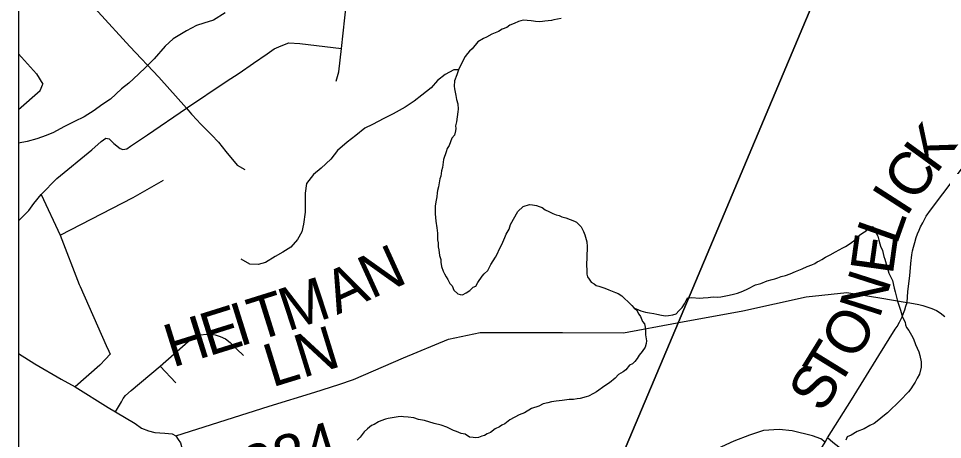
# Model space of a CAD drawing. Extents: x 0 to 34, y 0 to 22.
# Drawn here: x 2.1 to 3.321, y 17.998 to 18.554 of the extents above; entities that cross this region are included whole.
import ezdxf

# ---------------------------------------------------------------- set-up
doc = ezdxf.new("R2010")
doc.units = 0
for name, color, linetype in [('GM_X_Corporation', 7, 'Continuous'), ('GM_X_County_Road', 7, 'Continuous'), ('GM_X_County_Road_Text', 7, 'Continuous'), ('GM_X_Interchange_Ramps', 7, 'Continuous'), ('GM_X_Minor_River', 7, 'Continuous'), ('GM_X_Township_Road', 7, 'Continuous'), ('GM_X_Township_Road_Text', 7, 'Continuous'), ('SH_Data', 7, 'Continuous')]:
    doc.layers.add(name, color=color, linetype=linetype)

msp = doc.modelspace()

# ---------------------------------------------------------------- linework, layer by layer
at = {"layer": 'GM_X_Corporation'}
for points in [[(2.1, 20.9), (2.1, 16.0934), (2.225, 16.3897), (2.7544, 17.639), (2.811, 17.7726), (2.8255, 17.8068), (2.8709, 17.914), (2.886, 17.9497), (2.8909, 17.9612), (2.9719, 18.1533), (3.7872, 20.088)], [(3.7872, 20.088), (2.9719, 18.1533), (2.8909, 17.9612), (2.886, 17.9497), (2.8709, 17.914), (2.8255, 17.8068), (2.811, 17.7726), (2.7544, 17.639), (2.225, 16.3897), (2.1, 16.0934), (2.1, 14.8365)]]:
    msp.add_lwpolyline(points, dxfattribs=at)
at = {"layer": 'GM_X_County_Road'}
msp.add_line((3.2001, 18.0508), (3.2366, 18.1095), dxfattribs=at)
for points in [[(3.2805, 18.2449), (3.2809, 18.2475), (3.2822, 18.2524), (3.2838, 18.2586), (3.2859, 18.2652), (3.2875, 18.27), (3.2897, 18.275), (3.2913, 18.2791), (3.2945, 18.2845), (3.2966, 18.2888), (3.2991, 18.2932), (3.3047, 18.3011), (3.352, 18.3643), (3.3648, 18.3829), (3.3698, 18.3895), (3.388, 18.4133), (3.4253, 18.4636), (3.4871, 18.5467), (3.5036, 18.5662), (3.5105, 18.5772)], [(3.2736, 18.1791), (3.2748, 18.1939), (3.2774, 18.2146), (3.2786, 18.2309), (3.28, 18.2422), (3.2805, 18.2449)], [(3.2366, 18.1095), (3.258, 18.1439), (3.2604, 18.1477), (3.2638, 18.1534), (3.267, 18.1604), (3.269, 18.1654), (3.2706, 18.1697), (3.2721, 18.1744), (3.2736, 18.1791)], [(2.1, 18.1121), (2.1218, 18.0985), (2.1562, 18.078), (2.175, 18.0677), (2.2185, 18.0405), (2.228, 18.0349), (2.254, 18.0195), (2.2625, 18.0135), (2.2717, 18.0099), (2.2803, 18.0077), (2.2932, 18.0068), (2.3031, 18.0057), (2.3077, 18.003), (2.3108, 17.9984), (2.314, 17.9938), (2.3172, 17.982), (2.3194, 17.9708)], [(3.1365, 17.9476), (3.1388, 17.9514), (3.1653, 17.9947), (3.1688, 18.0005), (3.2001, 18.0508)]]:
    msp.add_lwpolyline(points, dxfattribs=at)
at = {"layer": 'GM_X_Interchange_Ramps'}
for points in [[(3.1653, 17.9947), (3.1597, 17.9994), (3.1486, 18.0033), (3.1221, 18.0097), (3.1047, 18.0116), (3.0841, 18.0102), (3.0655, 18.0041), (3.045, 17.9962), (3.0228, 17.9859), (3.005, 17.9792), (2.9809, 17.9725), (2.9579, 17.9681), (2.937, 17.9666), (2.9371, 17.959)], [(3.1927, 17.9832), (3.1837, 17.9882), (3.1758, 17.9944), (3.1688, 18.0005)]]:
    msp.add_lwpolyline(points, dxfattribs=at)
at = {"layer": 'GM_X_Minor_River'}
for points in [[(2.3731, 18.5619), (2.3577, 18.5523), (2.3447, 18.5483), (2.3351, 18.5451), (2.3221, 18.5381), (2.3044, 18.5274), (2.2939, 18.5177), (2.2792, 18.5012), (2.2683, 18.49), (2.2587, 18.4806), (2.2459, 18.4687), (2.2359, 18.4616), (2.2216, 18.4478), (2.21, 18.4404), (2.2, 18.433), (2.1869, 18.4245), (2.1739, 18.4183), (2.1601, 18.4113), (2.1462, 18.4039), (2.1367, 18.3999), (2.1244, 18.3955), (2.1114, 18.392), (2.1, 18.3895)], [(2.8167, 18.5545), (2.8071, 18.5524), (2.8041, 18.5517), (2.7953, 18.5507), (2.7922, 18.5503), (2.7881, 18.55), (2.7831, 18.5505), (2.7801, 18.5506), (2.7771, 18.5514), (2.7717, 18.5518), (2.7664, 18.5519), (2.7603, 18.5505), (2.7546, 18.5476), (2.7492, 18.5454), (2.745, 18.5424), (2.7389, 18.5402), (2.7339, 18.5373), (2.7251, 18.5336), (2.7181, 18.5296), (2.7143, 18.5281), (2.7066, 18.5233), (2.6993, 18.5143), (2.6958, 18.5113), (2.6931, 18.508), (2.69, 18.5042), (2.6868, 18.4986), (2.6845, 18.4937), (2.6825, 18.4895), (2.6813, 18.4865), (2.6789, 18.4801), (2.6761, 18.4721), (2.6756, 18.4649), (2.6759, 18.4615), (2.677, 18.4569), (2.6777, 18.4527), (2.6787, 18.4473), (2.6802, 18.4416), (2.6808, 18.4344), (2.6804, 18.431), (2.6786, 18.4177), (2.6774, 18.4124), (2.6777, 18.4089), (2.6773, 18.4059), (2.6757, 18.4002), (2.6726, 18.3961), (2.669, 18.3867), (2.6662, 18.3825), (2.665, 18.3784), (2.6614, 18.3682), (2.6601, 18.3575), (2.6589, 18.353), (2.658, 18.3462), (2.6564, 18.3424), (2.6547, 18.3321), (2.6535, 18.3272), (2.6531, 18.3242), (2.6526, 18.3189), (2.6514, 18.312), (2.6505, 18.3067), (2.6503, 18.2965), (2.6513, 18.2866), (2.6527, 18.2778), (2.6533, 18.2709)], [(2.6813, 18.4864), (2.675, 18.4863), (2.6635, 18.4804), (2.6534, 18.4726), (2.6449, 18.4629), (2.6326, 18.4532), (2.6225, 18.445), (2.6106, 18.4372), (2.5948, 18.4284), (2.5826, 18.4221), (2.5676, 18.4144), (2.5576, 18.4096), (2.5456, 18.3996), (2.5341, 18.391), (2.5213, 18.3802), (2.5124, 18.3686), (2.5, 18.3567), (2.4896, 18.3485), (2.4806, 18.3365), (2.4785, 18.3236), (2.4787, 18.3133), (2.4788, 18.2985), (2.4766, 18.2826), (2.4742, 18.2727), (2.4687, 18.2626), (2.4598, 18.2525), (2.449, 18.2458), (2.439, 18.2399), (2.4263, 18.2321), (2.4164, 18.2293), (2.4057, 18.2298), (2.394, 18.2365)], [(2.6533, 18.2709), (2.6533, 18.2671), (2.6536, 18.2622), (2.6543, 18.258), (2.6545, 18.2526), (2.6552, 18.2488), (2.6563, 18.2412), (2.6577, 18.2359), (2.658, 18.2324), (2.6587, 18.2267), (2.6608, 18.2206), (2.6627, 18.2171), (2.6649, 18.2133), (2.6671, 18.2098), (2.6697, 18.2045), (2.6727, 18.2014), (2.6749, 18.1956), (2.6805, 18.1906), (2.6835, 18.1898), (2.6866, 18.1893), (2.6912, 18.1919), (2.6962, 18.1952), (2.7004, 18.1994), (2.7039, 18.2008), (2.7066, 18.2057), (2.7124, 18.214), (2.7152, 18.217), (2.7198, 18.2215), (2.7237, 18.2294), (2.73, 18.2392), (2.7319, 18.2422), (2.7359, 18.2512), (2.7386, 18.2557), (2.7422, 18.2652), (2.7442, 18.2697), (2.7481, 18.2761), (2.7497, 18.2822), (2.7595, 18.2995), (2.7668, 18.3062), (2.7749, 18.3087), (2.779, 18.3083), (2.784, 18.3074), (2.7877, 18.3062), (2.7915, 18.3046), (2.7957, 18.3015), (2.8006, 18.2995), (2.8058, 18.2968), (2.81, 18.2952), (2.8142, 18.294), (2.8176, 18.2924), (2.8229, 18.2912), (2.8285, 18.2888), (2.8342, 18.2868), (2.8372, 18.2852), (2.8432, 18.279), (2.8461, 18.2729), (2.8479, 18.2687), (2.8508, 18.2595), (2.8511, 18.2534), (2.8509, 18.2389), (2.8503, 18.2294), (2.8506, 18.2211), (2.8509, 18.2169), (2.8516, 18.2131), (2.8538, 18.21), (2.8564, 18.2061), (2.8602, 18.2038), (2.8632, 18.2018), (2.8666, 18.201), (2.8745, 18.1982), (2.8798, 18.1958), (2.8885, 18.1923), (2.8919, 18.1911), (2.8968, 18.1879), (2.9001, 18.1852), (2.9058, 18.1798), (2.9102, 18.1755), (2.9132, 18.172), (2.9162, 18.1697), (2.9196, 18.1639), (2.9214, 18.1609), (2.9243, 18.1544), (2.9269, 18.1509), (2.9276, 18.1467), (2.9283, 18.1402), (2.9282, 18.1364), (2.9296, 18.1288), (2.9292, 18.125), (2.9276, 18.1201), (2.9237, 18.1144), (2.9198, 18.1096), (2.9174, 18.1054), (2.9143, 18.1013), (2.9108, 18.0983), (2.907, 18.0965), (2.9023, 18.0905), (2.8985, 18.0879), (2.8927, 18.0842), (2.8881, 18.0793), (2.8808, 18.073), (2.8746, 18.0693)], [(2.9137, 18.1716), (2.9189, 18.1697), (2.9219, 18.1681), (2.9249, 18.1673), (2.9283, 18.1665), (2.9336, 18.1656), (2.9393, 18.1647), (2.9431, 18.1639), (2.9492, 18.1627), (2.9545, 18.1618), (2.9587, 18.1621), (2.9644, 18.1628), (2.9686, 18.1642), (2.9721, 18.1684), (2.9767, 18.1728), (2.9795, 18.1777), (2.9818, 18.1819), (2.9838, 18.1856), (2.9895, 18.1859), (2.9994, 18.185), (3.0043, 18.1853), (3.0108, 18.1859), (3.0142, 18.1863), (3.018, 18.1866), (3.023, 18.1865), (3.0275, 18.1868), (3.0363, 18.1885), (3.0428, 18.1899), (3.0497, 18.1917), (3.0566, 18.1943), (3.0634, 18.1972), (3.0734, 18.2027), (3.0807, 18.2045), (3.0887, 18.2078), (3.0956, 18.2096), (3.099, 18.2106), (3.1028, 18.2117), (3.1074, 18.2135), (3.1132, 18.2149), (3.1193, 18.2171), (3.1262, 18.2204), (3.135, 18.2237), (3.1419, 18.2266), (3.148, 18.2292), (3.1518, 18.231), (3.1549, 18.2329), (3.158, 18.2343), (3.161, 18.2362), (3.166, 18.2391), (3.1722, 18.2424), (3.1791, 18.2461), (3.1887, 18.2513), (3.1925, 18.2531), (3.1971, 18.2565), (3.2033, 18.2605), (3.2064, 18.2639), (3.211, 18.268), (3.2152, 18.2714), (3.2195, 18.2739), (3.2233, 18.2781), (3.2283, 18.2795), (3.2302, 18.2764), (3.2324, 18.2718), (3.2349, 18.2668), (3.2364, 18.2615), (3.2378, 18.2569), (3.2385, 18.2538), (3.2411, 18.2481), (3.2429, 18.2401), (3.2443, 18.2366), (3.2472, 18.2255), (3.2497, 18.2179), (3.2512, 18.2144), (3.2545, 18.2083), (3.2566, 18.198), (3.258, 18.1934), (3.2612, 18.1812), (3.2638, 18.1731), (3.2649, 18.1693), (3.2677, 18.1598), (3.271, 18.1532), (3.2714, 18.1498), (3.2728, 18.1464), (3.2762, 18.1421), (3.2795, 18.136), (3.2821, 18.1314), (3.2846, 18.1237), (3.289, 18.1141), (3.2905, 18.1095), (3.2922, 18.1011), (3.2921, 18.0939), (3.29, 18.0848), (3.2869, 18.0795), (3.2845, 18.0743), (3.2818, 18.0701), (3.2787, 18.0652), (3.2756, 18.0615), (3.2721, 18.0577), (3.2682, 18.0533), (3.264, 18.0495), (3.2593, 18.0447)], [(2.8746, 18.0693), (2.8635, 18.0611), (2.8596, 18.0593), (2.8527, 18.0556), (2.8497, 18.0545), (2.842, 18.0523), (2.8378, 18.052), (2.8329, 18.0514), (2.8272, 18.0511), (2.818, 18.0497), (2.8104, 18.0491), (2.8039, 18.0481), (2.799, 18.047), (2.7932, 18.0456), (2.7871, 18.0426), (2.7775, 18.0394), (2.7683, 18.0338), (2.7614, 18.0309), (2.7492, 18.0243), (2.7422, 18.0191), (2.7384, 18.0173), (2.7353, 18.015), (2.7296, 18.0125), (2.7234, 18.0076), (2.7192, 18.0058), (2.7154, 18.0036), (2.7119, 18.0029), (2.7077, 18.0011), (2.7043, 18.0007), (2.7005, 18.0008), (2.6959, 18.0016), (2.6899, 18.0052), (2.6846, 18.0064), (2.6786, 18.0088), (2.6744, 18.0104), (2.671, 18.012), (2.6657, 18.0147), (2.6582, 18.0171), (2.6491, 18.0196), (2.6362, 18.0236), (2.6283, 18.0249), (2.6222, 18.0269), (2.6146, 18.0278), (2.6086, 18.0283), (2.6055, 18.0287), (2.6017, 18.0284), (2.5884, 18.026), (2.5849, 18.0253), (2.5784, 18.0231), (2.5754, 18.0216), (2.5696, 18.0183), (2.5662, 18.0168), (2.5608, 18.0124), (2.5565, 18.0086), (2.5515, 18.0015), (2.5472, 17.9974)], [(3.2593, 18.0447), (3.2535, 18.0391), (3.2477, 18.0338), (3.2416, 18.0286), (3.2366, 18.0245), (3.23, 18.0193), (3.2243, 18.0167), (3.217, 18.0123), (3.2078, 18.009), (3.1997, 18.0039), (3.1947, 18.0017), (3.1928, 17.9975)]]:
    msp.add_lwpolyline(points, dxfattribs=at)
at = {"layer": 'GM_X_Township_Road'}
msp.add_line((2.3079, 18.0731), (2.2871, 18.0954), dxfattribs=at)
for points in [[(2.1, 18.6779), (2.1215, 18.6553), (2.2472, 18.5175), (2.2854, 18.477), (2.322, 18.4357), (2.3286, 18.428)], [(2.5195, 18.4714), (2.5231, 18.4838), (2.5265, 18.5149), (2.5332, 18.5756)], [(2.1, 18.287), (2.1135, 18.3008), (2.1201, 18.3098), (2.1299, 18.3218), (2.1505, 18.3431), (2.1968, 18.3809), (2.2091, 18.3917), (2.2155, 18.3963), (2.2197, 18.3954), (2.2261, 18.3891), (2.2341, 18.3825), (2.2379, 18.3815), (2.2429, 18.3822), (2.248, 18.3856), (2.2702, 18.4006), (2.322, 18.4357), (2.3745, 18.4711), (2.3914, 18.4823), (2.4103, 18.4955), (2.4283, 18.5076), (2.4375, 18.5142), (2.4468, 18.5184), (2.457, 18.5221), (2.4715, 18.5214), (2.5265, 18.5149)], [(2.1, 18.5075), (2.1238, 18.4812), (2.1322, 18.4675)], [(2.1, 18.4343), (2.1288, 18.4591), (2.1322, 18.4675)], [(2.3286, 18.428), (2.3293, 18.4272), (2.3407, 18.4148), (2.3548, 18.4008), (2.364, 18.3912), (2.3738, 18.3788), (2.3888, 18.3607), (2.399, 18.3551)], [(2.1551, 18.268), (2.2514, 18.3178), (2.2915, 18.341)], [(2.1299, 18.3218), (2.1551, 18.268), (2.1803, 18.203)], [(2.1803, 18.203), (2.1814, 18.2002), (2.2156, 18.1224), (2.2195, 18.1148), (2.2212, 18.1112)], [(2.9701, 18.1524), (2.9721, 18.1528), (3.0567, 18.1681), (3.1402, 18.1868), (3.1941, 18.1923), (3.2376, 18.1854), (3.2736, 18.1791)], [(3.2736, 18.1791), (3.2772, 18.1787), (3.2892, 18.1765), (3.2945, 18.1754), (3.301, 18.1733), (3.3063, 18.1714), (3.3124, 18.1686), (3.3176, 18.1656), (3.3234, 18.161)], [(2.6084, 18.106), (2.6678, 18.1308), (2.7099, 18.1398), (2.7555, 18.1398), (2.8184, 18.1398), (2.8992, 18.1391), (2.9701, 18.1524)], [(2.2871, 18.0954), (2.324, 18.1278), (2.33, 18.1323), (2.335, 18.1343), (2.3403, 18.1364), (2.3481, 18.1373), (2.3541, 18.1371), (2.3598, 18.1364), (2.3665, 18.1345), (2.3735, 18.1312), (2.3798, 18.1263), (2.3884, 18.1176), (2.3971, 18.1091)], [(2.2212, 18.1112), (2.215, 18.1044), (2.2075, 18.0967), (2.175, 18.0677)], [(2.3077, 18.003), (2.4313, 18.0422), (2.4916, 18.0607), (2.523, 18.0709), (2.5425, 18.0776), (2.6084, 18.106)], [(2.228, 18.0349), (2.2333, 18.0438), (2.2359, 18.0483), (2.2381, 18.0525), (2.2415, 18.0566), (2.2489, 18.0631), (2.2871, 18.0954)]]:
    msp.add_lwpolyline(points, dxfattribs=at)
at = {"layer": 'SH_Data'}
msp.add_line((2.1, 20.9), (2.1, 14.1), dxfattribs=at)

# ---------------------------------------------------------------- texts
at = {"layer": 'GM_X_County_Road_Text'}
for s, rotation, p in [('K', 53.9279, (3.312, 18.3477)), ('C', 54.2019, (3.2847, 18.3099)), ('I', 57.2756, (3.2726, 18.2909)), ('L', 70.4442, (3.2599, 18.254)), ('E', 82.0621, (3.2547, 18.2148)), ('N', 72.2029, (3.2371, 18.1568)), ('O', 58.4844, (3.2047, 18.1007)), ('T', 58.3071, (3.1823, 18.0644)), ('S', 58.3069, (3.1622, 18.0318))]:
    msp.add_text(s, height=0.0568, rotation=rotation, dxfattribs=at).set_placement(p)
at = {"layer": 'GM_X_Township_Road_Text'}
for s, height, rotation, p in [('N', 0.0568, 24.5136, (2.566, 18.1835)), ('A', 0.0568, 24.7099, (2.5207, 18.1626)), ('M', 0.0568, 18.2265, (2.4555, 18.1408)), ('T', 0.0568, 17.3819, (2.4141, 18.1278)), ('E', 0.0568, 17.3819, (2.3513, 18.1081)), ('I', 0.0568, 17.3836, (2.3918, 18.1208)), ('H', 0.0568, 17.3831, (2.3036, 18.0932)), ('LN', 0.05682, 17.1429, (2.435, 18.067)), ('T-284', 0.05682, 17.3707, (2.3389, 17.91))]:
    msp.add_text(s, height=height, rotation=rotation, dxfattribs=at).set_placement(p)

doc.saveas('drawing.dxf')
